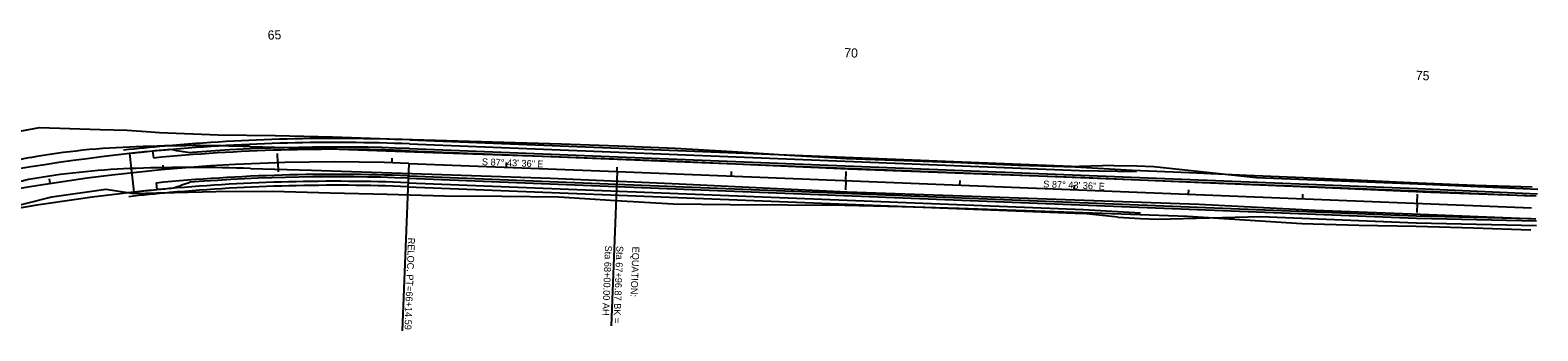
# Model space of a CAD drawing. Extents: x 1966723 to 1969285, y 1117431 to 1118041.
# Drawn here: x 1967966 to 1969285, y 1117777 to 1118041 of the extents above; entities that cross this region are included whole.
import ezdxf

# ---------------------------------------------------------------- set-up
doc = ezdxf.new("R2010")
doc.units = 0
for name, color, linetype in [('RD_EX_Road', 7, 'Continuous'), ('RD_EX_RW', 7, 'Continuous'), ('RD_HC_CL_Rel', 7, 'Continuous'), ('RD_HC_Data_Rel', 7, 'Continuous'), ('RD_HC_Data_Tic_Rel', 7, 'Continuous'), ('RD_HC_TX_Rel_Sta50', 7, 'Continuous'), ('RD_PD_Bridge', 7, 'Continuous'), ('RD_PD_EarthShd', 7, 'Continuous'), ('RD_PD_Final_TrvlWay', 7, 'Continuous'), ('RD_PD_PaveShd', 7, 'Continuous'), ('RD_Sketch3', 7, 'Continuous'), ('RD_Sketch4', 7, 'Continuous')]:
    doc.layers.add(name, color=color, linetype=linetype)

msp = doc.modelspace()

# ---------------------------------------------------------------- linework, layer by layer
at = {"layer": 'RD_EX_Road'}
for points in [[(1968158.7, 1117938.6), (1968212.1, 1117937.2), (1968318.8, 1117933.3), (1968422.8, 1117929.9), (1968530.5, 1117925.7)], [(1968530.5, 1117925.7), (1968682, 1117919), (1968783.2, 1117915.4), (1968888.6, 1117911.4), (1968991.2, 1117907.1), (1969092, 1117903.1), (1969191.1, 1117898.7), (1969283.3, 1117895.4)], [(1968159.2, 1117919.4), (1968212.5, 1117918), (1968317.5, 1117914.4), (1968421.5, 1117910.8), (1968527.8, 1117906.4)], [(1968527.8, 1117906.4), (1968680.8, 1117899.1), (1968781.7, 1117895.4), (1968887.9, 1117891.8), (1968988.7, 1117888.2), (1969090.1, 1117882.8), (1969189.3, 1117879), (1969282.9, 1117875.4)]]:
    msp.add_lwpolyline(points, dxfattribs=at)
for centre, radius, start, end in [((1968075.1, 1117320.6), 617.9, 91.4965, 100.1295), ((1968111.4, 1116608.6), 1330.8, 87.9632, 92.259), ((1968104.9, 1117261.1), 682.1, 101.7162, 109.6396), ((1968080.6, 1117363), 558.7, 101.3479, 110.7006), ((1968080.7, 1117246.5), 673.3, 91.837, 99.4057), ((1968107.6, 1116504.3), 1416, 87.9115, 91.9598)]:
    msp.add_arc(centre, radius, start, end, dxfattribs=at)
at = {"layer": 'RD_EX_RW'}
for points in [[(1967922.7, 1117945.6), (1967974.5, 1117955.3), (1968027.5, 1117953.6), (1968051.2, 1117952.9), (1968071.9, 1117951.6), (1968079.5, 1117951), (1968130.7, 1117949), (1968180.7, 1117948.4), (1968230.7, 1117947.1), (1968280.6, 1117945.5), (1968330.6, 1117944), (1968380.6, 1117942.5), (1968430.6, 1117940.9), (1968480.5, 1117939.1), (1968530.5, 1117937.2), (1968580.4, 1117934.2), (1968630.3, 1117931.2), (1968680.3, 1117928.2), (1968730.2, 1117926.4), (1968780.2, 1117924.7), (1968830.1, 1117922.4), (1968880.1, 1117920.9), (1968930, 1117917.9), (1968980, 1117915.8), (1969030, 1117913.7), (1969079.9, 1117911.5), (1969129.9, 1117909.2), (1969179.8, 1117906.8), (1969229.8, 1117904.9), (1969279.7, 1117903.2)], [(1967938.9, 1117882.9), (1967985.3, 1117894.6), (1968032.7, 1117901.4), (1968057.3, 1117897.4), (1968077.1, 1117898), (1968080.7, 1117898.1), (1968128.7, 1117899.3), (1968178.7, 1117899.4), (1968228.7, 1117898.2), (1968278.7, 1117896.8), (1968328.7, 1117895.5), (1968378.7, 1117895.2), (1968428.7, 1117894.5), (1968478.6, 1117891.5), (1968528.6, 1117888.4), (1968578.6, 1117888), (1968628.6, 1117887.7), (1968678.6, 1117887.4), (1968728.6, 1117886.1), (1968778.6, 1117884.7), (1968828.6, 1117882.9), (1968878.6, 1117881.2), (1968928.5, 1117879.4), (1968978.5, 1117877.6), (1969028.4, 1117874.5), (1969078.3, 1117871.2), (1969128.3, 1117869.8), (1969178.3, 1117868.8), (1969228.3, 1117867.4), (1969278.3, 1117865.8), (1969278.7, 1117865.8)]]:
    msp.add_lwpolyline(points, dxfattribs=at)
at = {"layer": 'RD_HC_CL_Rel'}
for p, q in [((1968297.5, 1117923.9), (1968479.6, 1117916.7)), ((1968479.6, 1117916.7), (1969279, 1117884.9))]:
    msp.add_line(p, q, dxfattribs=at)
msp.add_arc((1968232.6, 1116288.2), 1637, 87.7266, 111.9958, dxfattribs=at)
at = {"layer": 'RD_HC_Data_Rel'}
for p, q in [((1968297.5, 1117923.9), (1968291.7, 1117777.2)), ((1968479.6, 1117916.7), (1968474.3, 1117781.6))]:
    msp.add_line(p, q, dxfattribs=at)
at = {"layer": 'RD_HC_Data_Tic_Rel'}
for p, q in [((1968083.1, 1117918.4), (1968082.8, 1117922.3)), ((1968182.9, 1117924.4), (1968182.7, 1117932.4)), ((1968182.9, 1117924.4), (1968183.2, 1117916.5)), ((1968282.9, 1117924.4), (1968283, 1117928.4)), ((1968382.8, 1117920.5), (1968383, 1117924.5)), ((1967983.9, 1117906.2), (1967983.3, 1117910.2)), ((1968479.6, 1117916.7), (1968479.8, 1117920.7)), ((1968579.6, 1117912.7), (1968579.7, 1117916.7)), ((1968679.5, 1117908.7), (1968679.8, 1117916.7)), ((1968679.5, 1117908.7), (1968679.2, 1117900.8)), ((1968779.4, 1117904.8), (1968779.6, 1117908.8)), ((1968879.3, 1117900.8), (1968879.5, 1117904.8)), ((1968979.3, 1117896.8), (1968979.4, 1117900.8)), ((1969079.2, 1117892.9), (1969079.3, 1117896.9)), ((1969179.1, 1117888.9), (1969179.4, 1117896.9)), ((1969179.1, 1117888.9), (1969178.8, 1117880.9))]:
    msp.add_line(p, q, dxfattribs=at)
at = {"layer": 'RD_PD_Bridge'}
msp.add_line((1968053.4, 1117932.5), (1968057.1, 1117898.7), dxfattribs=at)
for radius in [1654, 1620]:
    msp.add_arc((1968232.6, 1116288.2), radius, 96.2174, 110.0424, dxfattribs=at)
at = {"layer": 'RD_PD_EarthShd'}
for p, q in [((1968298.3, 1117944.4), (1968884, 1117921.1)), ((1968914, 1117922.1), (1968884, 1117921.1)), ((1968914, 1117922.1), (1968934, 1117921.7)), ((1968934, 1117921.7), (1968949, 1117921.1)), ((1968949, 1117921.1), (1969038.7, 1117911.5)), ((1969038.7, 1117911.5), (1969179.8, 1117905.9)), ((1968296.7, 1117903.4), (1968887.4, 1117880)), ((1969179.8, 1117905.9), (1969284.7, 1117901.3)), ((1968917.3, 1117876.7), (1968887.4, 1117880)), ((1968917.3, 1117876.7), (1968937.2, 1117875.5)), ((1968937.2, 1117875.5), (1968952.2, 1117874.9)), ((1968952.2, 1117874.9), (1969042.4, 1117877.3)), ((1969042.4, 1117877.3), (1969178.4, 1117871.9)), ((1969178.5, 1117871.9), (1969283.5, 1117869.5))]:
    msp.add_line(p, q, dxfattribs=at)
for radius, start, end in [(1657.5, 95.1349, 96.3902), (1657.5, 87.7266, 95.1349), (1616.5, 95.1122, 96.3946), (1616.5, 87.7266, 95.1122)]:
    msp.add_arc((1968232.6, 1116288.2), radius, start, end, dxfattribs=at)
at = {"layer": 'RD_PD_Final_TrvlWay'}
for p, q in [((1968073.5, 1117934.5), (1968074.2, 1117928.6)), ((1968297.9, 1117934.9), (1968480.1, 1117927.7)), ((1968480.1, 1117927.7), (1969179.5, 1117899.9)), ((1968297.1, 1117912.9), (1968479.2, 1117905.7)), ((1968076.5, 1117906.7), (1968077.1, 1117900.7)), ((1968479.2, 1117905.7), (1969178.7, 1117877.9)), ((1969179.5, 1117899.9), (1969279.4, 1117895.6)), ((1969178.7, 1117877.9), (1969278.6, 1117875.6))]:
    msp.add_line(p, q, dxfattribs=at)
for radius, start, end in [(1648, 87.7266, 95.5156), (1654, 95.5174, 96.2174), (1626, 87.7266, 95.509), (1620, 95.5072, 96.2174)]:
    msp.add_arc((1968232.6, 1116288.2), radius, start, end, dxfattribs=at)
at = {"layer": 'RD_PD_PaveShd'}
for p, q in [((1968298, 1117936.9), (1968480.2, 1117929.7)), ((1968480.2, 1117929.7), (1969179.6, 1117901.9)), ((1968297, 1117910.9), (1968479.1, 1117903.7)), ((1968479.1, 1117903.7), (1969178.6, 1117875.9)), ((1969179.6, 1117901.9), (1969284.5, 1117897.3)), ((1969178.6, 1117875.9), (1969283.6, 1117873.5))]:
    msp.add_line(p, q, dxfattribs=at)
for centre, radius, start, end in [((1968232.6, 1116288.2), 1654, 94.9978, 95.5174), ((1967824.6, 1116351.9), 1605.9, 79.9714, 80.5425), ((1968232.6, 1116288.2), 1650, 87.7266, 94.4603), ((1968232.6, 1116288.2), 1624, 87.7266, 94.4603), ((1968232.6, 1116288.2), 1620, 94.9869, 95.5174), ((1968630.6, 1116423.5), 1573.7, 109.4622, 110.0242)]:
    msp.add_arc(centre, radius, start, end, dxfattribs=at)
at = {"layer": 'RD_Sketch3'}
for p, q in [((1968296.8, 1117906.9), (1968887.5, 1117883.5)), ((1968887.5, 1117883.5), (1968937.4, 1117880.5))]:
    msp.add_line(p, q, dxfattribs=at)
for start, end in [(95.1122, 96.3942), (87.7266, 95.1122)]:
    msp.add_arc((1968232.6, 1116288.2), 1620, start, end, dxfattribs=at)
at = {"layer": 'RD_Sketch4'}
for p, q in [((1968298.2, 1117940.9), (1968883.9, 1117917.6)), ((1968883.9, 1117917.6), (1968933.8, 1117916.7))]:
    msp.add_line(p, q, dxfattribs=at)
for start, end in [(95.1349, 96.3906), (87.7266, 95.1349)]:
    msp.add_arc((1968232.6, 1116288.2), 1654, start, end, dxfattribs=at)

# ---------------------------------------------------------------- texts
at = {"layer": 'RD_HC_Data_Rel'}
for s, rotation, p in [('S 87%%d 43\' 36" E', 357.7266, (1968361.3, 1117922.4)), ('S 87%%d 43\' 36" E', 357.7266, (1968852.1, 1117902.9)), ('RELOC. PT=66+14.59', 267.7266, (1968296.9, 1117858.9)), ('Sta 68+00.00 AH', 267.7266, (1968469.1, 1117852)), ('Sta 67+96.87 BK = ', 267.7266, (1968479.1, 1117851.7)), ('EQUATION:', 267.7266, (1968493.1, 1117851.1))]:
    msp.add_text(s, height=6, rotation=rotation, dxfattribs=at).set_placement(p)
at = {"layer": 'RD_HC_TX_Rel_Sta50'}
for s, rotation, p in [('65', 1.7374, (1968174.2, 1118032.2)), ('70', 357.7266, (1968678.1, 1118016.9)), ('75', 357.7266, (1969177.9, 1117997))]:
    msp.add_text(s, height=8, rotation=rotation, dxfattribs=at).set_placement(p)

doc.saveas('drawing.dxf')
